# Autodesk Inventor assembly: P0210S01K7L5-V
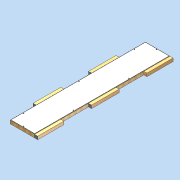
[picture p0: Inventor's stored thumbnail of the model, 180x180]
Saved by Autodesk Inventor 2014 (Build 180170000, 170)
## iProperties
Created: 2011-04
Part Number: P0210S01K7L5-V
Document SubType Name: Assembly
Designer: david.appleford
Mass: 34000 g
Surface Area: 46527.8 cm^2
Volume: 142203 cm^3
Density: 0.239095 g/cm^3
Description: 0.5w x 2.5w 01 Panel - 7 Locks 5 Lugs
Cost Center: £135.00
Justset: False
Author: david.appleford
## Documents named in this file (4)
- C:\Documents and Settings\john.everitt\Local Settings\My Documents\Vault\Production MkII\VIRTUAL ELEMENTS\Virtual Walls\Virtual Timber + MgO\P0210S01K7L5-V.iam
- C:\Documents and Settings\john.everitt\Local Settings\My Documents\Vault\Production MkII\VIRTUAL ELEMENTS\Virtual Lugs\Superceded Lugs\LA02C3V.ipt
- C:\Documents and Settings\john.everitt\Local Settings\My Documents\Vault\Production MkII\VIRTUAL ELEMENTS\Virtual Lugs\Superceded Lugs\LA02M3V.ipt
- C:\Documents and Settings\john.everitt\Local Settings\My Documents\Vault\Production MkII\VIRTUAL ELEMENTS\Virtual Walls\Virtual Timber + MgO\P0210S01K7-V.ipt
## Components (6 placed, 3 different names)
1. P0210S01K7-V:1 — Mate:1, Flush:1, Flush:2, Mate:5, Mate:6, Flush:9, Flush:10, Mate:7, Mate:8, Flush:11, Flush:12
2. LA02C3V:1 — Mate:1, Flush:1, Flush:2, Mate:9, Mate:13
3. LA02M3V:1 — Mate:6, Flush:9, Mate:12
4. LA02M3V:2 — Mate:5, Flush:10, Mate:12, Mate:13
5. LA02C3V:4 — Mate:8, Flush:12, Mate:10
6. LA02M3V:4 — Mate:7, Flush:11, Mate:9, Mate:10
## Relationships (15: Mate 9, Flush 6)
- Mate:1: P0210S01K7-V:1 ↔ LA02C3V:1
- Flush:1: P0210S01K7-V:1 ↔ LA02C3V:1
- Flush:2: P0210S01K7-V:1 ↔ LA02C3V:1
- Mate:5: P0210S01K7-V:1 ↔ LA02M3V:2
- Mate:6: P0210S01K7-V:1 ↔ LA02M3V:1
- Flush:9: P0210S01K7-V:1 ↔ LA02M3V:1
- Flush:10: P0210S01K7-V:1 ↔ LA02M3V:2
- Mate:7: P0210S01K7-V:1 ↔ LA02M3V:4
- Mate:8: P0210S01K7-V:1 ↔ LA02C3V:4
- Flush:11: P0210S01K7-V:1 ↔ LA02M3V:4
- Flush:12: P0210S01K7-V:1 ↔ LA02C3V:4
- Mate:9: LA02C3V:1 ↔ LA02M3V:4
- Mate:10: LA02C3V:4 ↔ LA02M3V:4
- Mate:12: LA02M3V:1 ↔ LA02M3V:2
- Mate:13: LA02C3V:1 ↔ LA02M3V:2
## Named parameters: t = 1 mm, Cl = 2 mm
